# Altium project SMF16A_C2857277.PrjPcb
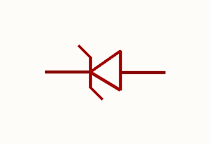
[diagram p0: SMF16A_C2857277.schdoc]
1 sheet, 1 parts. Net scope: global (net labels, ports and power ports of the same name join across sheets).

## Sheet SMF16A_C2857277.schdoc
size 127 x 101 mm

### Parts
D?  smf16a_c2857277  [SOD-123FL_L2.8-W1.9-LS3.7-RD]  (value not drawn)

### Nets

Not connected (* = marked no-connect by the designer): D? 1(C) 2(A)

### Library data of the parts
D? = smf16a_c2857277: 极性:单向;反向截止电压(Vrwm):16V;钳位电压:26V;峰值脉冲电流(Ipp):7.7A;峰值脉冲功率(Ppp):200W@10/1000us;击穿电压(VBR):17.8V;; Manufacturer: JSMSEMI(杰盛微); ManufacturerPart: SMF16A; AddInBom: yes; ModelId: ee80cc4b5e2f4a0b8a944bbfc66c96ba; ModelTransform: 141.732,74.803,0,0,0,0,0,0,0; Polarity: 单向; Reverse Stand-Off Voltage (Vrwm): 16V; Clamping Voltage: 26V; Peak Pulse Current (Ipp): 7.7A; Voltage - Breakdown: 17.8V; Reverse Leakage Current (Ir): 1uA; Number of Channels: 单路; Type: TVS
